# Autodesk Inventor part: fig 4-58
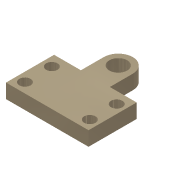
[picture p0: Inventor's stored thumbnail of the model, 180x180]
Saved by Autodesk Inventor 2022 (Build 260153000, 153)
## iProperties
Created: 2004-05
Part Number: fig 4-58
Document SubType Name: Modeling
Designer: CADCIM Technologies
Manufacturer: Standard
Standards Organization: Custom
Density: 1 g/cm^3
Material: Generic
Appearance: Metal-Titanium (Polished)
Author: CADCIM Technologies
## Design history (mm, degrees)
sketch "Sketch1"
  geometry: L1 (39.729, 55.62)-(39.729, 42.054); L2 (39.729, 42.054)-(23.837, 42.054); L3 (23.837, 42.054)-(23.837, 13.516); L4 (23.837, 13.516)-(72.804, 13.516); L5 (72.804, 13.516)-(72.804, 42.054); L6 (72.804, 42.054)-(56.912, 42.054); L7 (56.912, 42.054)-(56.912, 55.62); C1 r 3.354 at (29.212, 35.336); C2 r 3.354 at (29.212, 19.383); C3 r 3.354 at (67.7, 35.336); C4 r 3.354 at (67.7, 19.383); C5 r 5.297 at (48.32, 55.62); A1 r 8.592 centre (48.32, 55.62) between (56.912, 55.62) and (39.729, 55.62)
  constraints: 14 end point, 6 centre point, 4 parallel, 2 equal length, 2 horizontal alignment, 2 point on circle, 2 tangent, 2 vertical alignment, 1 coincident, 1 collinear, 1 perpendicular, 1 vertical
extrude "Extrusion1" new body sketch "Sketch1" distance "d0" = 8.5; taper "d1" = 0 deg
body "Solid1"
